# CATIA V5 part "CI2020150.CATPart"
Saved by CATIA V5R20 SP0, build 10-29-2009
Part number: CI2020150
Bounding box of the stored display mesh (mm): x -19 to 19, y -14.509 to 180, z -26.066 to 21.271
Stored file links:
  C:\Users\Raffaele\Desktop\3D X SITO CF\BOLEX\19-INCLINED ASSEMBLY REF_CI\CI2020150.CATPart

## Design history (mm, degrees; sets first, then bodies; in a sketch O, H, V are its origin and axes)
Set1
  DatumSurface1 to DatumSurface16 "MANIFOLD_SOLID_BREP #387"
  DatumSurface17 to DatumSurface39 "MANIFOLD_SOLID_BREP #1116"
Body1 (main body)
